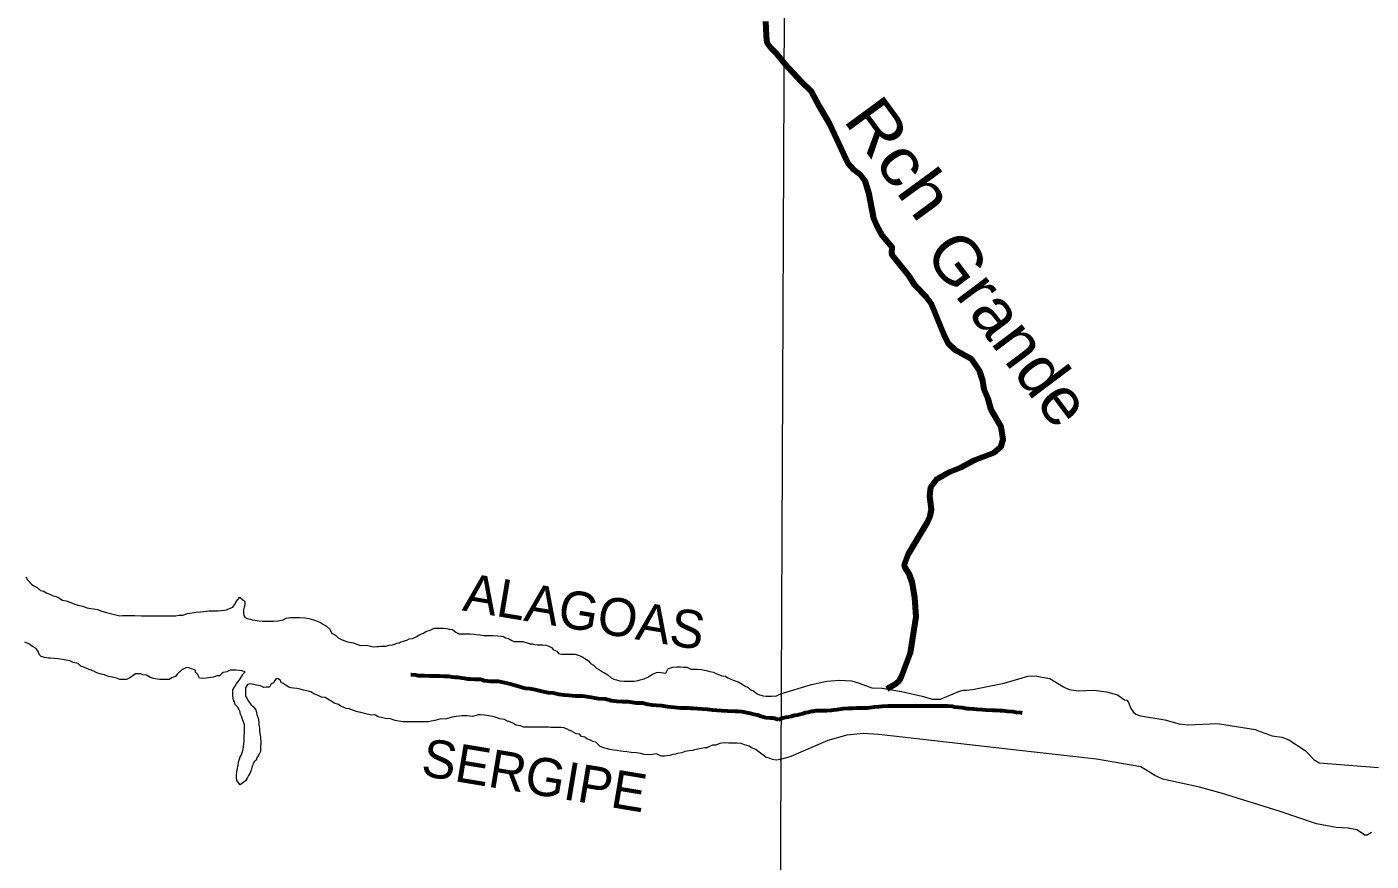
# Model space of a CAD drawing. Extents: x 553962 to 842807, y 8883888 to 9032388.
# Drawn here: x 656600 to 670746, y 8920745 to 8929526 of the extents above; entities that cross this region are included whole.
import ezdxf
from ezdxf.enums import TextEntityAlignment as Align

# ---------------------------------------------------------------- set-up
doc = ezdxf.new("R2010")
doc.units = 0
doc.header["$LTSCALE"] = 20
doc.header["$PDMODE"] = 32
doc.header["$PDSIZE"] = 10
doc.linetypes.add('LONG_DASH_SHORT_DASH', pattern=[9.9, 6, -1.2, 1.5, -1.2])
for name, color, linetype, lineweight in [('1', 7, 'Continuous', 13), ('24', 7, 'Continuous', 25), ('25', 7, 'Continuous', 13), ('53', 7, 'Continuous', 106), ('7', 7, 'LONG_DASH_SHORT_DASH', 60)]:
    doc.layers.add(name, color=color, linetype=linetype, lineweight=lineweight)
doc.layers.add('42', color=7, linetype='Continuous')
doc.layers.add('49', color=7, linetype='Continuous')

msp = doc.modelspace()

# ---------------------------------------------------------------- linework, layer by layer
at = {"layer": '1'}
msp.add_lwpolyline([(664968.2, 9023436.8), (664657.1, 8949509.04), (664397.13, 8890880.24)], dxfattribs=at)
at = {"layer": '24'}
msp.add_line((666737.23, 8925710.67), (666737.92, 8925710.12), dxfattribs=at)
for points in [[(665884.55, 8926902.08), (665710.74, 8927118.58), (665703.49, 8927141.57), (665707.31, 8927207.31), (665604.73, 8927327.25), (665543.5, 8927435.1), (665514.23, 8927508.85), (665462.23, 8927764.76), (665420.03, 8927905.88), (665377.45, 8927963.9), (665304.37, 8928016.17), (665243.3, 8928087.83), (665050.78, 8928503.22), (664941.49, 8928686.57), (664858.29, 8928844.55), (664746.48, 8928950.8), (664577.75, 8929135.39), (664488.88, 8929245.34), (664434.08, 8929300.68), (664391.81, 8929358.47), (664382.12, 8929428.59), (664380, 8929511.2), (664377.84, 8929583.79)], [(665654.06, 8922558.08), (665747.43, 8922613.38), (665782.6, 8922644.93), (665804.2, 8922685), (665898.25, 8922936.99), (665956.62, 8923316.75), (665944.27, 8923521.01), (665915.89, 8923680.26), (665887.05, 8923762.64), (665837.76, 8923840.38), (665834.88, 8923868.6), (665876.02, 8923981.1), (666075.94, 8924311.24), (666104.41, 8924374.85), (666118.21, 8924447.79), (666103.21, 8924589.12), (666111.82, 8924680), (666180.15, 8924767.65), (666303.31, 8924840.66), (666423.21, 8924888.8), (666566.96, 8924965.36), (666778.14, 8925046.49), (666849.39, 8925104.55), (666875.5, 8925182.52), (666852.32, 8925317.15), (666747.44, 8925494.9), (666714.93, 8925611.21), (666673.96, 8925709.53), (666660.9, 8925800.79), (666626.84, 8925897.59), (666539.34, 8926027.54), (666367.33, 8926123.44), (666298.19, 8926188.38), (666251.52, 8926283.41), (666120.58, 8926610.26), (666067.38, 8926681.34), (665942.59, 8926807.87), (665884.55, 8926902.08)], [(665804.2, 8922685), (665782.6, 8922644.93), (665747.43, 8922613.38), (665654.06, 8922558.08)]]:
    msp.add_lwpolyline(points, dxfattribs=at)
msp.add_point((664531.11, 8921815.38), dxfattribs=at)
at = {"layer": '25'}
for points in [[(656587.52, 8923737.13), (656607.29, 8923704.46), (656646.98, 8923661.63), (656671.84, 8923641.44), (656706.71, 8923623.69), (656744, 8923593.4), (656778.98, 8923588.16), (656803.85, 8923570.47), (656848.74, 8923552.65), (656876.14, 8923537.44), (656908.61, 8923532.22), (656936, 8923517.02), (656975.83, 8923491.72), (657013.31, 8923486.47), (657063.18, 8923466.11), (657105.58, 8923450.81), (657152.98, 8923435.47), (657190.44, 8923427.72), (657230.32, 8923409.92), (657272.8, 8923404.64), (657302.77, 8923399.43), (657345.25, 8923394.14), (657377.66, 8923381.41), (657437.56, 8923363.49), (657494.97, 8923348.09), (657577.34, 8923327.52), (657604.88, 8923329.84), (657624.89, 8923329.71), (657664.9, 8923329.44), (657732.43, 8923328.99), (657804.95, 8923328.51), (657862.48, 8923328.13), (657887.49, 8923327.97), (657925, 8923327.72), (657945.01, 8923327.59), (657992.53, 8923327.27), (658027.54, 8923327.04), (658082.57, 8923326.68), (658110.07, 8923326.49), (658167.6, 8923326.11), (658197.66, 8923333.43), (658242.68, 8923333.13), (658290.35, 8923352.84), (658337.93, 8923360.04), (658382.99, 8923364.74), (658428.04, 8923369.46), (658460.59, 8923374.25), (658518.15, 8923378.87), (658568.17, 8923378.54), (658610.71, 8923380.76), (658645.74, 8923383.04), (658680.79, 8923387.81), (658700.82, 8923390.18), (658740.96, 8923407.44), (658768.55, 8923417.27), (658791.33, 8923452.17), (658801.54, 8923479.64), (658839.4, 8923524.45), (658894.06, 8923476.53), (658893.81, 8923443.98), (658886.12, 8923419), (658878.4, 8923391.51), (658878.25, 8923371.48), (658878.1, 8923351.45), (658882.95, 8923331.4), (658895.3, 8923311.28), (658917.72, 8923298.62), (658952.67, 8923290.88), (658975.14, 8923285.72), (658997.61, 8923280.57), (659045.08, 8923272.74), (659075.09, 8923272.54), (659120.11, 8923272.24), (659142.61, 8923272.1), (659177.63, 8923271.86), (659200.14, 8923271.72), (659240.17, 8923273.95), (659262.72, 8923278.81), (659295.27, 8923283.6), (659327.91, 8923300.91), (659370.49, 8923308.14), (659425.53, 8923310.28), (659473.05, 8923309.97), (659528.05, 8923307.1), (659565.5, 8923299.34), (659617.91, 8923283.97), (659655.33, 8923271.21), (659690.23, 8923255.96), (659720.09, 8923235.73), (659752.47, 8923217.99), (659789.73, 8923185.2), (659806.96, 8923147.53), (659849.3, 8923124.72), (659876.59, 8923094.49), (659918.95, 8923074.19), (659963.83, 8923056.37), (659988.79, 8923048.69), (660038.77, 8923043.35), (660078.65, 8923025.57), (660111.09, 8923015.33)], [(660111.09, 8923015.33), (660173.63, 8923017.42), (660243.53, 8922999.44), (660281.08, 8923004.2), (660301.08, 8923004.06), (660323.61, 8923006.42), (660356.13, 8923006.21), (660376.15, 8923008.57), (660411.25, 8923018.36), (660448.8, 8923023.12), (660471.36, 8923030.48), (660493.93, 8923037.84), (660516.48, 8923042.7), (660536.56, 8923052.57), (660564.13, 8923059.9), (660596.71, 8923069.7), (660624.34, 8923084.54), (660656.89, 8923089.33), (660704.56, 8923109.05), (660729.71, 8923126.4), (660774.86, 8923143.63), (660797.5, 8923161), (660842.63, 8923175.73), (660885.32, 8923197.98), (660915.33, 8923197.78), (660940.34, 8923197.61), (660980.36, 8923197.35), (661020.36, 8923194.58), (661042.8, 8923186.92), (661077.78, 8923181.68), (661115.1, 8923156.4), (661147.48, 8923138.66), (661187.5, 8923138.4), (661207.51, 8923138.27), (661245.02, 8923138.02), (661265.03, 8923137.89), (661305, 8923132.61), (661327.49, 8923129.96), (661364.99, 8923127.21), (661407.45, 8923119.42), (661447.46, 8923119.15), (661472.48, 8923118.99), (661507.49, 8923118.75), (661557.49, 8923115.92), (661592.48, 8923113.19), (661614.97, 8923110.54), (661637.37, 8923095.36), (661667.32, 8923087.66), (661702.18, 8923067.4), (661724.62, 8923057.23), (661754.63, 8923057.03), (661819.66, 8923056.6), (661897.01, 8923033.56), (661919.5, 8923030.91), (661941.97, 8923025.75), (661971.96, 8923023.05), (662009.48, 8923022.8), (662029.49, 8923022.67), (662061.98, 8923019.95), (662086.92, 8923009.77), (662121.8, 8922992.02), (662141.63, 8922969.36), (662176.53, 8922954.1), (662193.85, 8922928.95), (662226.32, 8922923.73), (662258.84, 8922923.52), (662293.85, 8922923.28), (662313.86, 8922923.15), (662333.86, 8922923.02), (662371.38, 8922922.77), (662401.31, 8922912.56), (662438.73, 8922899.79), (662471.09, 8922879.55), (662508.42, 8922854.27), (662530.7, 8922824.08), (662563.09, 8922808.84), (662592.86, 8922776.1), (662625.24, 8922758.36), (662657.6, 8922738.12), (662680.04, 8922727.96), (662712.39, 8922707.72), (662747.16, 8922674.94), (662777.06, 8922659.72), (662804.52, 8922652.03), (662839.47, 8922644.29), (662884.45, 8922638.98), (662916.96, 8922638.77), (662936.96, 8922638.64), (662969.48, 8922638.42), (662992.01, 8922640.77), (663032.06, 8922645.51), (663054.63, 8922652.88), (663094.72, 8922662.63), (663134.87, 8922679.89), (663155.01, 8922697.28), (663182.63, 8922712.12), (663225.28, 8922729.36), (663250.33, 8922734.2), (663325.28, 8922723.69), (663348.16, 8922771.1), (663378.23, 8922778.42)], [(658099.97, 8922655.61), (658064.96, 8922655.85), (658042.45, 8922655.99), (657999.93, 8922656.28), (657972.43, 8922658.96), (657932.48, 8922666.74), (657900.06, 8922679.47), (657860.21, 8922702.26), (657820.24, 8922707.54), (657797.79, 8922715.2), (657762.77, 8922715.43), (657742.77, 8922715.56), (657707.58, 8922693.26), (657684.92, 8922673.38), (657649.77, 8922656.09), (657629.76, 8922656.22), (657609.75, 8922656.35), (657577.25, 8922656.57), (657542.34, 8922671.82), (657499.91, 8922682.12), (657459.95, 8922689.89), (657415.06, 8922707.71), (657382.59, 8922712.94), (657335.18, 8922728.27), (657305.3, 8922745.99), (657255.4, 8922761.34), (657205.53, 8922781.7), (657168.13, 8922796.97), (657138.33, 8922824.71), (657085.9, 8922837.57), (657051, 8922852.82), (657011.04, 8922860.6), (656973.59, 8922868.36), (656928.61, 8922873.66), (656888.63, 8922878.93), (656848.63, 8922881.7), (656826.13, 8922881.85), (656786.15, 8922887.12), (656751.21, 8922897.37), (656731.36, 8922917.53), (656719.12, 8922952.66), (656696.84, 8922982.85), (656659.48, 8923003.12), (656619.67, 8923030.93), (656577.29, 8923048.73)], [(658980.7, 8922371.9), (659007.96, 8922339.17), (659017.72, 8922306.56), (659024.97, 8922273.97), (659032.32, 8922253.89), (659039.48, 8922208.78), (659041.79, 8922183.73), (659044.14, 8922163.68), (659046.47, 8922141.14), (659048.73, 8922108.57), (659055.94, 8922070.98), (659058.29, 8922050.93), (659058.14, 8922030.9), (659060.49, 8922010.86), (659060.32, 8921988.33), (659060.07, 8921955.79), (659059.8, 8921920.74), (659057.15, 8921900.73), (659046.98, 8921878.26), (659034.28, 8921853.31), (659021.6, 8921830.86), (659013.93, 8921808.38), (658991.28, 8921791.01), (658981.09, 8921766.04), (658970.92, 8921743.57), (658960.61, 8921703.59), (658945.34, 8921668.64), (658932.66, 8921646.19), (658922.48, 8921623.73), (658899.73, 8921591.33), (658844.36, 8921546.63), (658809.71, 8921594.43), (658807.46, 8921626.99), (658807.63, 8921649.52), (658807.9, 8921684.57), (658815.7, 8921724.57), (658823.41, 8921752.06), (658828.68, 8921787.07), (658838.92, 8921817.05), (658844.11, 8921842.05), (658856.79, 8921864.5), (658869.52, 8921894.46), (658874.75, 8921924.46), (658879.92, 8921946.96), (658882.69, 8921981.99), (658887.92, 8922012), (658888.15, 8922042.04), (658888.32, 8922064.57), (658888.57, 8922097.12), (658888.83, 8922132.16), (658888.98, 8922152.19), (658889.21, 8922182.23), (658884.36, 8922202.3), (658864.7, 8922247.49), (658859.87, 8922270.05), (658845.07, 8922297.69), (658842.73, 8922317.73), (658835.38, 8922337.81), (658818.12, 8922370.47), (658793.28, 8922393.16), (658785.98, 8922420.75), (658773.63, 8922440.86), (658771.28, 8922460.9), (658766.53, 8922493.48), (658766.75, 8922523.52), (658766.95, 8922548.56), (658784.66, 8922575.98), (658802.42, 8922608.41), (658827.68, 8922640.79), (658845.36, 8922663.2), (658863.07, 8922690.62), (658875.79, 8922718.08), (658895.95, 8922737.97), (658861, 8922748.22), (658836.03, 8922753.39), (658803.52, 8922753.61), (658778.52, 8922753.77), (658738.5, 8922754.04), (658705.85, 8922736.73), (658665.78, 8922729.48), (658645.64, 8922712.09), (658625.5, 8922694.7), (658602.99, 8922694.85), (658580.44, 8922689.99), (658560.37, 8922682.61), (658510.3, 8922675.43), (658485.25, 8922670.59), (658452.72, 8922668.3), (658417.72, 8922671.04), (658395.54, 8922713.74), (658375.68, 8922733.9), (658373.33, 8922753.95), (658343.4, 8922764.16), (658303.5, 8922779.44), (658281.01, 8922782.1), (658243.38, 8922767.32), (658223.25, 8922752.44), (658182.94, 8922712.65), (658162.76, 8922690.25), (658122.61, 8922672.99), (658099.97, 8922655.61)], [(663378.23, 8922778.42), (663398.29, 8922785.8), (663440.84, 8922790.52), (663478.36, 8922790.27), (663513.35, 8922787.54), (663545.87, 8922787.32), (663588.23, 8922767.01), (663623.23, 8922764.28), (663658.24, 8922764.05), (663698.24, 8922761.28), (663730.7, 8922753.55), (663760.67, 8922748.35), (663785.62, 8922740.67), (663825.59, 8922735.4), (663850.49, 8922720.22), (663890.39, 8922704.93), (663912.84, 8922697.27), (663950.32, 8922692.01), (663977.7, 8922674.31), (664032.53, 8922648.91), (664084.92, 8922631.04), (664127.26, 8922608.23), (664152.14, 8922590.54), (664192.02, 8922572.75), (664211.87, 8922552.59), (664249.25, 8922534.82), (664286.54, 8922504.53), (664309, 8922496.87), (664348.93, 8922486.59), (664381.41, 8922481.37), (664416.43, 8922481.14), (664436.43, 8922481.01), (664461.46, 8922483.34), (664481.46, 8922483.21), (664531.11, 8922504.72), (664855.66, 8922606.05), (665018.2, 8922640.05), (665151.93, 8922649.77), (665276.55, 8922642.57), (665359.45, 8922619.84)], [(662255.43, 8922147.44), (662220.43, 8922150.18), (662177.94, 8922152.96), (662152.93, 8922153.13), (662112.92, 8922153.39), (662087.91, 8922153.56), (662027.88, 8922153.96), (661975.36, 8922154.3), (661940.35, 8922154.54), (661900.34, 8922154.8), (661872.82, 8922154.98), (661830.3, 8922155.26), (661790.4, 8922170.55), (661750.43, 8922175.82), (661715.56, 8922196.08), (661683.16, 8922211.32), (661648.23, 8922221.56), (661625.84, 8922236.73), (661578.35, 8922242.05), (661538.45, 8922257.33), (661516, 8922264.99), (661483.52, 8922270.22), (661441.07, 8922278.01), (661416.09, 8922283.18), (661373.58, 8922283.46), (661351.07, 8922283.61), (661290.93, 8922268.99), (661233.45, 8922274.38), (661178.43, 8922274.74), (661150.9, 8922272.42), (661115.84, 8922267.64), (661075.77, 8922260.4), (661015.61, 8922243.27), (660945.55, 8922238.73), (660892.92, 8922224.05), (660852.84, 8922216.81), (660825.3, 8922211.98), (660772.75, 8922209.83), (660732.73, 8922210.09), (660682.71, 8922210.42), (660637.7, 8922210.72), (660610.19, 8922210.9), (660560.17, 8922211.23), (660510.21, 8922219.08), (660475.25, 8922226.82), (660425.37, 8922244.67), (660375.37, 8922247.51), (660342.91, 8922255.23), (660295.45, 8922263.06), (660268.07, 8922280.76), (660213.09, 8922286.13), (660165.63, 8922293.96), (660113.22, 8922309.33), (660080.77, 8922317.05), (660035.86, 8922332.37), (659995.96, 8922347.65), (659958.48, 8922352.91), (659936.03, 8922360.57), (659903.63, 8922375.81), (659878.75, 8922393.49), (659833.85, 8922408.81), (659808.96, 8922424), (659766.63, 8922449.31), (659739.26, 8922467.02), (659699.28, 8922472.29), (659656.91, 8922492.6), (659619.5, 8922505.36), (659587.13, 8922525.61), (659547.21, 8922538.39), (659509.75, 8922546.15), (659477.32, 8922556.38), (659442.34, 8922561.62), (659407.37, 8922566.85), (659382.38, 8922569.52), (659354.92, 8922577.21), (659330.03, 8922592.4), (659297.68, 8922615.15), (659275.25, 8922625.31), (659267.9, 8922645.38), (659245.55, 8922665.56), (659223.05, 8922668.21), (659210.38, 8922645.76), (659195.21, 8922623.33), (659170.1, 8922610.98), (659152.33, 8922576.05), (659117.31, 8922576.28), (659092.28, 8922573.94), (659059.88, 8922589.18), (659037.41, 8922594.33), (659002.46, 8922602.08), (658967.48, 8922607.32), (658944.99, 8922609.97), (658919.95, 8922605.13), (658902.15, 8922567.69), (658901.95, 8922540.15), (658899.16, 8922502.62), (658901.51, 8922482.57), (658913.84, 8922459.96), (658933.59, 8922427.29), (658955.84, 8922392.09), (658980.7, 8922371.9)], [(665807.24, 8922530.49), (665805.27, 8922529.01), (666021.23, 8922480.78), (666128.09, 8922448.38), (666212.62, 8922450.21), (666414.11, 8922533.64), (666451.65, 8922544.89), (666486.42, 8922546.22), (666551.55, 8922551.37), (666883.25, 8922619.33), (667134.87, 8922692.25), (667207.82, 8922696.79), (667365.96, 8922668.83), (667507, 8922579.59), (667567.86, 8922550.44), (667666.3, 8922536.68), (667827.1, 8922544.76), (667960.23, 8922528.29), (668076.17, 8922494.14), (668149.9, 8922444.51), (668175.27, 8922440.95), (668193.39, 8922414.23), (668215.84, 8922353.06), (668240.75, 8922316.83), (668270.27, 8922290.59), (668317.34, 8922273.49), (668576.32, 8922231.45), (668724.66, 8922190.82), (668817.5, 8922180.44), (669130.48, 8922192.71), (669529.97, 8922132.15)], [(665359.45, 8922619.84), (665492.33, 8922568.26), (665600.03, 8922565.93), (665805.27, 8922529.01)], [(663096.18, 8921869), (663056.22, 8921876.77), (663013.77, 8921884.56), (662958.79, 8921889.93), (662913.8, 8921895.24), (662873.81, 8921898.01), (662851.34, 8921903.16), (662811.36, 8921908.43), (662773.89, 8921913.69), (662733.93, 8921921.46), (662696.47, 8921929.22), (662671.52, 8921936.9), (662634.11, 8921952.17), (662611.76, 8921972.34), (662586.94, 8921997.54), (662556.96, 8922002.75), (662529.57, 8922017.95), (662492.17, 8922033.22), (662469.79, 8922050.89), (662434.82, 8922056.13), (662415, 8922081.3), (662380.01, 8922084.03), (662332.7, 8922111.88), (662292.84, 8922132.18), (662255.43, 8922147.44)], [(670612.99, 8921062.45), (670594.59, 8921075.06), (670505.69, 8921092.14), (670378.91, 8921097.71), (670172.47, 8921136.14), (669790.16, 8921267.99), (669181.56, 8921455.52), (668940.41, 8921522.25), (668553.32, 8921609.07), (668470.57, 8921645.96), (668322.79, 8921739.34), (667855.13, 8921816.82), (666980.89, 8921915.91), (665565.88, 8922078.05), (665402.46, 8922087.85), (665227.79, 8922071.54), (665027.5, 8922015.61), (664640.89, 8921845.5), (664531.11, 8921815.38)], [(669529.97, 8922132.15), (669551.53, 8922120.61), (669703.5, 8922065.45), (669805.25, 8922048.52), (669880.31, 8922022.19), (670051.29, 8921908.81), (670147.45, 8921810.77), (670198.87, 8921779.06), (670825.12, 8921728.99)], [(664531.11, 8921815.38), (664483.83, 8921807.24), (664446.37, 8921815), (664411.45, 8921827.75), (664379, 8921835.47), (664344.19, 8921863.24), (664321.82, 8921880.92), (664291.98, 8921903.65), (664269.58, 8921918.82), (664224.7, 8921936.64), (664202.32, 8921954.31), (664152.41, 8921969.66), (664117.52, 8921984.91), (664070.02, 8921987.73), (664027.5, 8921988.01), (663982.48, 8921988.31), (663937.47, 8921988.61), (663892.41, 8921983.9), (663849.74, 8921964.15), (663814.73, 8921964.38), (663792.16, 8921957.02), (663754.5, 8921937.24), (663734.48, 8921937.38), (663696.91, 8921930.11), (663661.85, 8921922.84), (663626.77, 8921915.56), (663606.72, 8921910.68), (663571.68, 8921905.91), (663524.1, 8921898.71), (663491.47, 8921883.91), (663446.42, 8921879.2), (663426.35, 8921871.82), (663396.3, 8921867.01), (663366.21, 8921857.2), (663333.66, 8921852.4), (663311.14, 8921850.05), (663276.12, 8921850.28), (663226.29, 8921875.65), (663156.17, 8921863.59), (663096.18, 8921869)], [(670751.55, 8921047.3), (670704.91, 8921020.18), (670678.61, 8921017.47), (670612.99, 8921062.45)]]:
    msp.add_lwpolyline(points, dxfattribs=at)
msp.add_point((664531.11, 8921815.38), dxfattribs=at)
at = {"layer": '53'}
for points in [[(665884.55, 8926902.08), (665710.74, 8927118.58), (665703.49, 8927141.57), (665707.31, 8927207.31), (665604.73, 8927327.25), (665543.5, 8927435.1), (665514.23, 8927508.85), (665462.23, 8927764.76), (665420.03, 8927905.88), (665377.45, 8927963.9), (665304.37, 8928016.17), (665243.3, 8928087.83), (665050.78, 8928503.22), (664941.49, 8928686.57), (664858.29, 8928844.55), (664746.48, 8928950.8), (664577.75, 8929135.39), (664488.88, 8929245.34), (664434.08, 8929300.68), (664391.81, 8929358.47), (664382.12, 8929428.59), (664380, 8929511.2), (664377.84, 8929583.79)], [(665654.06, 8922558.08), (665747.43, 8922613.38), (665782.6, 8922644.93), (665804.2, 8922685), (665898.25, 8922936.99), (665956.62, 8923316.75), (665944.27, 8923521.01), (665915.89, 8923680.26), (665887.05, 8923762.64), (665837.76, 8923840.38), (665834.88, 8923868.6), (665876.02, 8923981.1), (666075.94, 8924311.24), (666104.41, 8924374.85), (666118.21, 8924447.79), (666103.21, 8924589.12), (666111.82, 8924680), (666180.15, 8924767.65), (666303.31, 8924840.66), (666423.21, 8924888.8), (666566.96, 8924965.36), (666778.14, 8925046.49), (666849.39, 8925104.55), (666875.5, 8925182.52), (666852.32, 8925317.15), (666747.44, 8925494.9), (666714.93, 8925611.21), (666673.96, 8925709.53), (666660.9, 8925800.79), (666626.84, 8925897.59), (666539.34, 8926027.54), (666367.33, 8926123.44), (666298.19, 8926188.38), (666251.52, 8926283.41), (666120.58, 8926610.26), (666067.38, 8926681.34), (665942.59, 8926807.87), (665884.55, 8926902.08)]]:
    msp.add_lwpolyline(points, dxfattribs=at)
at = {"layer": '7'}
for points in [[(663706.25, 8922345.57), (663656.27, 8922348.33), (663616.28, 8922351.06), (663591.28, 8922351.19), (663566.29, 8922353.82), (663526.3, 8922354.03), (663483.81, 8922356.76), (663411.35, 8922362.14), (663341.38, 8922367.52), (663281.47, 8922380.35), (663226.48, 8922383.14), (663181.52, 8922388.39), (663134.05, 8922393.65), (663081.64, 8922406.43), (663011.66, 8922409.3), (662926.75, 8922422.26), (662864.25, 8922422.6), (662806.76, 8922425.4), (662751.8, 8922430.7), (662691.91, 8922448.53), (662616.95, 8922453.93), (662539.54, 8922466.85), (662447.14, 8922482.36), (662372.13, 8922482.76), (662304.67, 8922488.12), (662249.71, 8922493.41), (662197.24, 8922498.7), (662142.34, 8922514), (662087.36, 8922516.79), (662019.95, 8922529.66), (661950.06, 8922547.55), (661892.64, 8922560.37), (661845.17, 8922563.12), (661797.75, 8922575.88), (661750.35, 8922591.14), (661690.46, 8922606.47), (661625.55, 8922621.83), (661563.14, 8922634.68), (661478.16, 8922637.63), (661413.19, 8922642.98), (661378.29, 8922655.67), (661338.27, 8922655.89), (661310.77, 8922656.03), (661268.29, 8922658.76), (661238.31, 8922661.42), (661205.84, 8922666.6), (661175.86, 8922669.26), (661135.91, 8922676.98), (661105.93, 8922679.64), (661075.95, 8922682.3), (661040.98, 8922687.49), (660993.48, 8922687.74), (660941, 8922690.52), (660893.52, 8922693.27), (660841.02, 8922693.55), (660786.02, 8922693.84), (660746.04, 8922696.56), (660718.53, 8922696.7), (660691.07, 8922701.85), (660648.59, 8922704.58), (660641.67, 8922706.35)], [(666977.62, 8922317.6), (666919.09, 8922320.15), (666870.75, 8922327.82), (666842.76, 8922327.82), (666799.5, 8922330.38), (666761.33, 8922330.38), (666692.63, 8922335.49), (666657.01, 8922338.04), (666595.94, 8922340.6), (666565.4, 8922345.71), (666519.6, 8922348.26), (666496.7, 8922348.26), (666461.08, 8922355.93), (666440.72, 8922358.48), (666405.1, 8922361.04), (666366.93, 8922366.15), (666338.94, 8922371.27), (666290.59, 8922376.38), (666226.98, 8922376.37), (666168.45, 8922376.37), (666140.47, 8922376.37), (666092.12, 8922376.37), (666061.59, 8922376.37), (665980.16, 8922376.37), (665944.54, 8922376.37), (665886.02, 8922376.37), (665855.49, 8922376.37), (665799.51, 8922376.37), (665768.97, 8922376.37), (665697.73, 8922376.37), (665659.56, 8922376.37), (665601.04, 8922371.25), (665570.51, 8922368.7), (665519.62, 8922366.14), (665494.18, 8922361.03), (665443.29, 8922355.91), (665400.03, 8922355.91), (665377.13, 8922355.91), (665333.88, 8922355.91), (665293.17, 8922350.8), (665244.82, 8922350.8), (665188.84, 8922348.24), (665145.59, 8922340.57), (665122.69, 8922338.01), (665087.07, 8922335.46), (665066.72, 8922330.34), (665018.37, 8922327.79), (664987.84, 8922327.79), (664962.39, 8922327.79), (664934.4, 8922327.79), (664903.87, 8922327.78), (664875.88, 8922320.11), (664855.53, 8922320.11), (664819.91, 8922309.89), (664791.92, 8922304.78), (664763.94, 8922297.11), (664733.41, 8922289.44), (664707.96, 8922281.77), (664677.43, 8922276.65), (664646.9, 8922268.99), (664616.37, 8922261.32), (664585.84, 8922256.2), (664555.31, 8922251.09), (664555.31, 8922251.09), (664555.31, 8922251.09)], [(664555.31, 8922251.09), (664510.51, 8922233.71), (664455.62, 8922249.02), (664420.63, 8922251.7), (664375.65, 8922254.44), (664325.74, 8922267.22), (664288.34, 8922282.43), (664250.88, 8922287.64), (664213.46, 8922300.35), (664176, 8922305.55), (664128.57, 8922318.31), (664086.07, 8922318.53), (664048.59, 8922321.23), (663973.61, 8922324.14), (663908.62, 8922326.98), (663861.16, 8922332.24), (663816.17, 8922334.98), (663763.71, 8922340.26), (663706.25, 8922345.57)], [(667073.54, 8922301.59), (667059.05, 8922304.82), (667005.61, 8922309.93), (666977.62, 8922317.6)]]:
    msp.add_lwpolyline(points, dxfattribs=at)

# ---------------------------------------------------------------- texts
at = {"layer": '42'}
for s, p in [('ALAGOAS', (662435.02, 8923174.8)), ('SERGIPE', (661908.64, 8921452.52))]:
    msp.add_text(s, height=400, rotation=350.533, dxfattribs=at).set_placement(p, align=Align.CENTER)
at = {"layer": '49'}
for s, rotation, width, p in [('Rch', 306.272, 1.15, (665180.93, 8928547.66)), ('Grande', 306.886, 1.05, (666032.22, 8927138.08))]:
    msp.add_text(s, height=500, rotation=rotation, dxfattribs=dict(at, width=width)).set_placement(p)

doc.saveas('drawing.dxf')
